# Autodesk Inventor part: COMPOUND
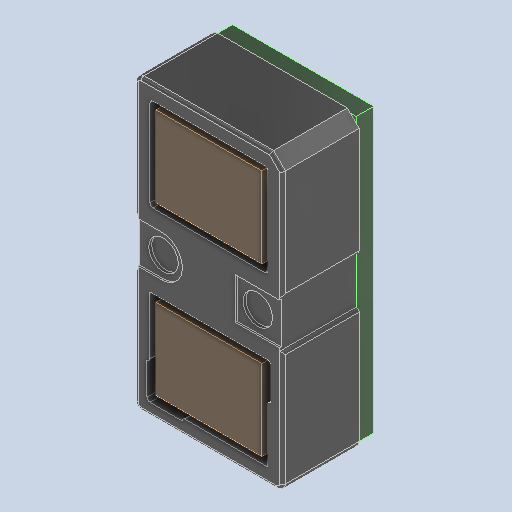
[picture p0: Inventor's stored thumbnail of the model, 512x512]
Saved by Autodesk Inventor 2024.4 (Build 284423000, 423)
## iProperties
Created: 2025-05
Part Number: COMPOUND
Material: Generic
Document SubType Name: Modeling
Designer: AdminForWorker
Density: 1 g/cm^3
Appearance: Default
Title: COMPOUND (1)
Author: AdminForWorker
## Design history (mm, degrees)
feature "Body1"
feature "Body2"
feature "Body3"
feature "Body4"
feature "Body5"
feature "Body6"
feature "Body7"
feature "Body8"
feature "Body9"
feature "Body10"
feature "Body11"
feature "Body12"
feature "Body13"
feature "Body14"
feature "Body15"
feature "Body16"
body "Solid1"
body "Solid2"
body "Solid3"
body "Solid4"
body "Solid5"
body "Solid6"
body "Solid7"
body "Solid8"
body "Solid9"
body "Solid10"
body "Solid11"
body "Solid12"
body "Solid13"
body "Solid14"
body "Solid15"
body "Solid16"
